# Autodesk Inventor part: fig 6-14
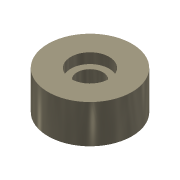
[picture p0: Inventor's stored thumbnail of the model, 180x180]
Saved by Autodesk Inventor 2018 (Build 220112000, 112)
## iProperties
Shininess: 65.0
Angle Display Precision: 2
Document Length Units: 11269
Document Angle Units: 11279
Document Time Units: 11290
Document Mass Units: 11283
Document Length Units Precision: 3
Document Angle Units Precision: 2
Created: 2001-11
Part Number: fig 6-14
Document SubType Name: Modeling
Designer: Renu Muthoo
Density: 1 g/cm^3
Material: Generic
Appearance: Metal-Titanium (Polished)
Density: 0.0
Volumn: 0.0
Area: 0.0
PropertySet Name: Model Information
Control State: 0
Master: False
Checked Out: False
Author: Renu Muthoo
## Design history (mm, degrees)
sketch "Sketch1"
  geometry: C1 r 16.401 at (0, 0)
  constraints: 1 centre point
extrude "Extrusion1" new body sketch "Sketch1" distance "d0" = 15; taper "d1" = 0 deg
hole "Hole3" diameter "d18" = 10.106; stored, may be unused: countersink angle "d22" = 90 deg, drill point angle "d24" = 118 deg; dims "d16" = 10, "d17" = 10, "d19" = 6, "d20" = 15, "d21" = 4, "d23" = 10
body "Solid1"
